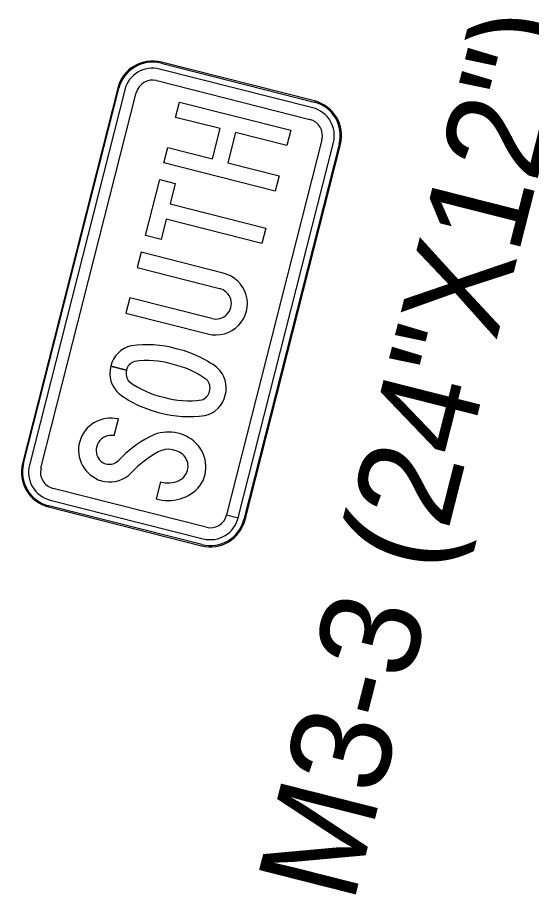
# Model space of a CAD drawing. Extents: x 670257 to 671518, y 737783 to 738188.
# Drawn here: x 670295.772 to 670297.06, y 738152.056 to 738154.257 of the extents above; entities that cross this region are included whole.
import ezdxf

# ---------------------------------------------------------------- set-up
doc = ezdxf.new("R2010")
doc.units = 0
doc.layers.add('R_SIGN_ANNOT', color=7, linetype='Continuous')
doc.layers.add('R_SIGN_HWY102', color=7, linetype='Continuous')

msp = doc.modelspace()

# ---------------------------------------------------------------- linework, layer by layer
at = {"layer": 'R_SIGN_HWY102'}
for p, q in [((670296.1321, 738154.1419), (670296.1321, 738154.1419)), ((670296.1321, 738154.1419), (670296.5157, 738154.0446)), ((670296.1329, 738154.1448), (670296.1328, 738154.1448)), ((670296.1329, 738154.1448), (670296.1328, 738154.1448)), ((670296.5165, 738154.0475), (670296.1329, 738154.1448)), ((670296.5165, 738154.0475), (670296.1329, 738154.1448)), ((670296.512, 738154.03), (670296.1284, 738154.1273)), ((670296.1284, 738154.1273), (670296.1284, 738154.1273)), ((670296.121, 738154.0983), (670296.1211, 738154.0983)), ((670296.1211, 738154.0983), (670296.5047, 738154.001)), ((670296.0236, 738154.0797), (670295.7847, 738153.1379)), ((670296.0236, 738154.0797), (670295.7847, 738153.1379)), ((670295.7876, 738153.1372), (670296.0265, 738154.0789)), ((670296.041, 738154.0753), (670295.8021, 738153.1335)), ((670296.0236, 738154.0797), (670296.0236, 738154.0797)), ((670296.0236, 738154.0797), (670296.0236, 738154.0797)), ((670296.0265, 738154.0789), (670296.0265, 738154.0789)), ((670296.041, 738154.0753), (670296.041, 738154.0753)), ((670295.8312, 738153.1261), (670296.0701, 738154.0679)), ((670296.0701, 738154.0679), (670296.07, 738154.0679)), ((670296.512, 738154.03), (670296.512, 738154.03)), ((670296.5157, 738154.0446), (670296.5157, 738154.0446)), ((670296.5165, 738154.0475), (670296.5165, 738154.0475)), ((670296.5165, 738154.0475), (670296.5165, 738154.0475)), ((670296.5047, 738154.001), (670296.5047, 738154.001)), ((670296.535, 738153.95), (670296.2962, 738153.0085)), ((670296.3253, 738153.0011), (670296.5641, 738153.9426)), ((670296.5786, 738153.9389), (670296.3397, 738152.9972)), ((670296.535, 738153.95), (670296.535, 738153.95)), ((670296.5641, 738153.9426), (670296.5641, 738153.9426)), ((670296.5786, 738153.9389), (670296.5786, 738153.9389)), ((670296.3427, 738152.9964), (670296.5815, 738153.9382)), ((670296.3427, 738152.9964), (670296.5815, 738153.9382)), ((670296.5815, 738153.9382), (670296.5815, 738153.9382)), ((670296.5815, 738153.9382), (670296.5815, 738153.9382)), ((670296.0437, 738153.5149), (670296.2494, 738153.4628)), ((670296.0437, 738153.5149), (670296.2494, 738153.4628)), ((670296.0437, 738153.5149), (670296.2494, 738153.4628)), ((670296.0455, 738153.3718), (670296.0063, 738153.3817)), ((670296.0063, 738153.3817), (670296.0455, 738153.3718)), ((670296.0455, 738153.3718), (670296.0063, 738153.3817)), ((670296.0063, 738153.3817), (670296.0455, 738153.3718)), ((670296.0146, 738153.2076), (670296.0252, 738153.2495)), ((670296.0146, 738153.2076), (670296.0252, 738153.2495)), ((670296.0146, 738153.2076), (670296.0252, 738153.2495)), ((670295.7847, 738153.1379), (670295.7847, 738153.1379)), ((670295.7847, 738153.1379), (670295.7847, 738153.1379)), ((670295.7876, 738153.1372), (670295.7876, 738153.1372)), ((670295.8021, 738153.1335), (670295.8021, 738153.1335)), ((670295.8312, 738153.1261), (670295.8312, 738153.1261)), ((670296.1307, 738153.0915), (670296.1199, 738153.049)), ((670296.1307, 738153.0915), (670296.1199, 738153.049)), ((670296.1307, 738153.0915), (670296.1199, 738153.049)), ((670296.2452, 738152.9778), (670295.8615, 738153.0751)), ((670295.8615, 738153.0751), (670295.8615, 738153.0751)), ((670295.8542, 738153.046), (670295.8542, 738153.046)), ((670295.8542, 738153.046), (670296.2378, 738152.9487)), ((670295.8497, 738153.0286), (670295.8498, 738153.0286)), ((670295.8497, 738153.0286), (670295.8498, 738153.0286)), ((670295.8498, 738153.0286), (670296.2334, 738152.9313)), ((670295.8498, 738153.0286), (670296.2334, 738152.9313)), ((670296.2341, 738152.9342), (670295.8505, 738153.0315)), ((670295.8505, 738153.0315), (670295.8505, 738153.0315)), ((670296.2962, 738153.0085), (670296.3253, 738153.0011)), ((670296.3252, 738153.0008), (670296.2962, 738153.0082)), ((670296.2962, 738153.0082), (670296.2962, 738153.0082)), ((670296.3252, 738153.0008), (670296.3252, 738153.0008)), ((670296.3397, 738152.9972), (670296.3427, 738152.9964)), ((670296.3427, 738152.9964), (670296.3397, 738152.9971)), ((670296.3397, 738152.9971), (670296.3397, 738152.9971)), ((670296.3426, 738152.9964), (670296.3427, 738152.9964)), ((670296.2452, 738152.9778), (670296.2452, 738152.9778)), ((670296.2378, 738152.9487), (670296.2378, 738152.9487)), ((670296.2334, 738152.9313), (670296.2334, 738152.9313)), ((670296.2334, 738152.9313), (670296.2334, 738152.9313)), ((670296.2341, 738152.9342), (670296.2341, 738152.9342))]:
    msp.add_line(p, q, dxfattribs=at)
for points in [[(670296.1393, 738153.892), (670296.1491, 738153.9305), (670296.2606, 738153.9022), (670296.2798, 738153.9778), (670296.1682, 738154.0061), (670296.178, 738154.0446), (670296.4569, 738153.9738), (670296.4472, 738153.9354), (670296.3189, 738153.9679), (670296.2997, 738153.8923), (670296.428, 738153.8597), (670296.4182, 738153.8213)], [(670296.1393, 738153.892), (670296.1491, 738153.9305), (670296.2606, 738153.9022), (670296.2798, 738153.9778), (670296.1682, 738154.0061), (670296.178, 738154.0446), (670296.4569, 738153.9738), (670296.4472, 738153.9354), (670296.3189, 738153.9679), (670296.2997, 738153.8923), (670296.428, 738153.8597), (670296.4182, 738153.8213)], [(670296.1393, 738153.892), (670296.1491, 738153.9305), (670296.2606, 738153.9022), (670296.2798, 738153.9778), (670296.1682, 738154.0061), (670296.178, 738154.0446), (670296.4569, 738153.9738), (670296.4472, 738153.9354), (670296.3189, 738153.9679), (670296.2997, 738153.8923), (670296.428, 738153.8597), (670296.4182, 738153.8213)], [(670296.145, 738153.7505), (670296.1321, 738153.6997), (670296.093, 738153.7096), (670296.1286, 738153.8498), (670296.1676, 738153.8399), (670296.1547, 738153.7891), (670296.3946, 738153.7282), (670296.3849, 738153.6897)], [(670296.145, 738153.7505), (670296.1321, 738153.6997), (670296.093, 738153.7096), (670296.1286, 738153.8498), (670296.1676, 738153.8399), (670296.1547, 738153.7891), (670296.3946, 738153.7282), (670296.3849, 738153.6897)], [(670296.145, 738153.7505), (670296.1321, 738153.6997), (670296.093, 738153.7096), (670296.1286, 738153.8498), (670296.1676, 738153.8399), (670296.1547, 738153.7891), (670296.3946, 738153.7282), (670296.3849, 738153.6897)]]:
    msp.add_lwpolyline(points, close=True, dxfattribs=at)
for points in [[(670296.2881, 738153.6153), (670296.0824, 738153.6675), (670296.0726, 738153.629), (670296.2783, 738153.5768)], [(670296.2881, 738153.6153), (670296.0824, 738153.6675), (670296.0726, 738153.629), (670296.2783, 738153.5768)], [(670296.2881, 738153.6153), (670296.0824, 738153.6675), (670296.0726, 738153.629), (670296.2783, 738153.5768)], [(670296.2591, 738153.5012), (670296.0534, 738153.5534), (670296.0437, 738153.5149)], [(670296.2591, 738153.5012), (670296.0534, 738153.5534), (670296.0437, 738153.5149)], [(670296.2591, 738153.5012), (670296.0534, 738153.5534), (670296.0437, 738153.5149)]]:
    msp.add_lwpolyline(points, dxfattribs=at)
for centre, major_axis, ratio, start_param, end_param in [((670296.1107, 738154.0576), (0.0221, 0.0872), 0.999584, 0, 1.570796), ((670296.1107, 738154.0576), (0.0221, 0.0872), 0.999584, 0, 1.570796), ((670296.1107, 738154.0576), (0.0214, 0.0843), 0.999584, 0, 1.570796), ((670296.1107, 738154.0576), (0.0177, 0.0698), 0.999584, 0, 1.570796), ((670296.1107, 738154.0576), (0.0103, 0.0407), 0.999584, 0, 1.570796), ((670296.4943, 738153.9603), (0.0177, 0.0698), 0.999584, 4.712389, 6.283185), ((670296.4943, 738153.9603), (0.0214, 0.0843), 0.999584, 4.712389, 6.283185), ((670296.4943, 738153.9603), (0.0221, 0.0872), 0.999584, 4.712389, 6.283185), ((670296.4943, 738153.9603), (0.0221, 0.0872), 0.999584, 4.712389, 6.283185), ((670296.4943, 738153.9603), (0.0103, 0.0407), 0.999584, 4.712389, 6.283185), ((670296.2687, 738153.539), (-0.0774, 0.0196), 0.985401, 1.570796, 4.712389), ((670296.2687, 738153.539), (-0.0774, 0.0196), 0.985401, 1.570796, 4.712389), ((670296.2687, 738153.539), (-0.0774, 0.0196), 0.985401, 1.570796, 4.712389), ((670296.2687, 738153.539), (-0.0384, 0.0097), 0.985401, 1.570796, 4.712389), ((670296.2687, 738153.539), (-0.0384, 0.0097), 0.985401, 1.570796, 4.712389), ((670296.2687, 738153.539), (-0.0384, 0.0097), 0.985401, 1.570796, 4.712389), ((670296.0725, 738153.3673), (-0.0657, 0.0167), 0.987317, 5.182411, 6.318105), ((670296.0725, 738153.3673), (-0.0657, 0.0167), 0.987317, 5.182411, 6.317893), ((670296.0725, 738153.3673), (-0.0657, 0.0167), 0.987317, 5.182411, 6.317893), ((670296.0985, 738153.1659), (-0.2645, 0.0671), 0.987317, 4.692766, 5.109028), ((670296.0985, 738153.1659), (-0.2645, 0.0671), 0.987317, 4.692766, 5.109028), ((670296.0985, 738153.1659), (-0.2645, 0.0671), 0.987317, 4.692766, 5.109028), ((670296.1089, 738153.1633), (-0.2645, 0.0671), 0.987317, 4.31575, 4.732012), ((670296.1089, 738153.1633), (-0.2645, 0.0671), 0.987317, 4.31575, 4.732012), ((670296.1089, 738153.1633), (-0.2645, 0.0671), 0.987317, 4.31575, 4.732012), ((670296.074, 738153.3661), (-0.0281, 0.0071), 0.987317, 5.258281, 6.33678), ((670296.074, 738153.3661), (-0.0281, 0.0071), 0.987317, 5.258281, 6.336283), ((670296.074, 738153.3661), (-0.0281, 0.0071), 0.987317, 5.258281, 6.336283), ((670296.0986, 738153.1841), (-0.2078, 0.0527), 0.987317, 4.667051, 5.113562), ((670296.0986, 738153.1841), (-0.2078, 0.0527), 0.987317, 4.667051, 5.113562), ((670296.0986, 738153.1841), (-0.2078, 0.0527), 0.987317, 4.667051, 5.113562), ((670296.0714, 738153.3628), (-0.0657, 0.0167), 0.987317, 6.248265, 7.383959), ((670296.0714, 738153.3628), (-0.0657, 0.0167), 0.987317, 6.248265, 7.383959), ((670296.0714, 738153.3628), (-0.0657, 0.0167), 0.987317, 6.248265, 7.383959), ((670296.0732, 738153.3631), (-0.0281, 0.0071), 0.987317, 6.22959, 7.30809), ((670296.0732, 738153.3631), (-0.0281, 0.0071), 0.987317, 6.22959, 7.30809), ((670296.0732, 738153.3631), (-0.0281, 0.0071), 0.987317, 6.22959, 7.30809), ((670296.1175, 738153.1793), (-0.2078, 0.0527), 0.987317, 4.311216, 4.757727), ((670296.1175, 738153.1793), (-0.2078, 0.0527), 0.987317, 4.311216, 4.757727), ((670296.1175, 738153.1793), (-0.2078, 0.0527), 0.987317, 4.311216, 4.757727), ((670296.2277, 738153.3279), (-0.0657, 0.0167), 0.987317, 3.106673, 4.242367), ((670296.2277, 738153.3279), (-0.0657, 0.0167), 0.987317, 3.106673, 4.242367), ((670296.2277, 738153.3279), (-0.0657, 0.0167), 0.987317, 3.106673, 4.242367), ((670296.2259, 738153.3276), (-0.0281, 0.0071), 0.987317, 3.087997, 4.166497), ((670296.2259, 738153.3276), (-0.0281, 0.0071), 0.987317, 3.087997, 4.166497), ((670296.2259, 738153.3276), (-0.0281, 0.0071), 0.987317, 3.087997, 4.166497), ((670296.1816, 738153.5114), (-0.2078, 0.0527), 0.987317, 1.169623, 1.616135), ((670296.1816, 738153.5114), (-0.2078, 0.0527), 0.987317, 1.169623, 1.616135), ((670296.1816, 738153.5114), (-0.2078, 0.0527), 0.987317, 1.169623, 1.616135), ((670296.1902, 738153.5274), (-0.2645, 0.0671), 0.987317, 1.174158, 1.59042), ((670296.1902, 738153.5274), (-0.2645, 0.0671), 0.987317, 1.174158, 1.59042), ((670296.1902, 738153.5274), (-0.2645, 0.0671), 0.987317, 1.174158, 1.59042), ((670296.2005, 738153.5066), (-0.2078, 0.0527), 0.987317, 1.525458, 1.97197), ((670296.2005, 738153.5066), (-0.2078, 0.0527), 0.987317, 1.525458, 1.97197), ((670296.2005, 738153.5066), (-0.2078, 0.0527), 0.987317, 1.525458, 1.97197), ((670296.2251, 738153.3246), (-0.0281, 0.0071), 0.987317, 2.116688, 3.195188), ((670296.2251, 738153.3246), (-0.0281, 0.0071), 0.987317, 2.116688, 3.195188), ((670296.2251, 738153.3246), (-0.0281, 0.0071), 0.987317, 2.116688, 3.195188), ((670296.2266, 738153.3234), (-0.0657, 0.0167), 0.987317, 2.040819, 3.176513), ((670296.2266, 738153.3234), (-0.0657, 0.0167), 0.987317, 2.040819, 3.176513), ((670296.2266, 738153.3234), (-0.0657, 0.0167), 0.987317, 2.040819, 3.176513), ((670296.0073, 738153.1708), (-0.0796, 0.0202), 0.981581, 4.736267, 7.790596), ((670296.0073, 738153.1708), (-0.0796, 0.0202), 0.981581, 4.736267, 7.790596), ((670296.0073, 738153.1708), (-0.0796, 0.0202), 0.981581, 4.736267, 7.790596), ((670296.2006, 738153.5248), (-0.2645, 0.0671), 0.987317, 1.551173, 1.967435), ((670296.2006, 738153.5248), (-0.2645, 0.0671), 0.987317, 1.551173, 1.967435), ((670296.2006, 738153.5248), (-0.2645, 0.0671), 0.987317, 1.551173, 1.967435), ((670296.1513, 738153.1201), (-0.0951, 0.0241), 0.981581, 4.260987, 5.485755), ((670296.1513, 738153.1201), (-0.0951, 0.0241), 0.981581, 4.260987, 5.485755), ((670296.1513, 738153.1201), (-0.0951, 0.0241), 0.981581, 4.260987, 5.485755), ((670296.0081, 738153.1702), (-0.0374, 0.0095), 0.981581, 4.786904, 7.140738), ((670296.0081, 738153.1702), (-0.0374, 0.0095), 0.981581, 4.786904, 7.140738), ((670296.0081, 738153.1702), (-0.0374, 0.0095), 0.981581, 4.786904, 7.140738), ((670296.249, 738152.9415), (-0.2944, 0.0747), 0.981581, 5.462886, 5.782242), ((670296.249, 738152.9415), (-0.2944, 0.0747), 0.981581, 5.462886, 5.782242), ((670296.249, 738152.9415), (-0.2944, 0.0747), 0.981581, 5.462886, 5.782242), ((670296.1584, 738153.1296), (-0.0835, 0.0212), 0.981581, 2.786047, 4.251692), ((670296.1584, 738153.1296), (-0.0835, 0.0212), 0.981581, 2.786047, 4.251692), ((670296.1584, 738153.1296), (-0.0835, 0.0212), 0.981581, 2.786047, 4.251692), ((670296.151, 738153.1194), (-0.0531, 0.0135), 0.981581, 4.254409, 5.632398), ((670296.151, 738153.1194), (-0.0531, 0.0135), 0.981581, 4.254409, 5.632398), ((670296.151, 738153.1194), (-0.0531, 0.0135), 0.981581, 4.254409, 5.632398), ((670296.0022, 738153.1668), (-0.0309, 0.0078), 0.981581, 0.87378, 2.656959), ((670296.0022, 738153.1668), (-0.0309, 0.0078), 0.981581, 0.87378, 2.656959), ((670296.0022, 738153.1668), (-0.0309, 0.0078), 0.981581, 0.87378, 2.656959), ((670296.2866, 738152.893), (-0.3108, 0.0788), 0.981581, 5.515137, 5.786988), ((670296.2866, 738152.893), (-0.3108, 0.0788), 0.981581, 5.515137, 5.786988), ((670296.2866, 738152.893), (-0.3108, 0.0788), 0.981581, 5.515137, 5.786988), ((670296.1597, 738153.1309), (-0.0389, 0.0099), 0.981581, 2.261787, 4.23006), ((670296.1597, 738153.1309), (-0.0389, 0.0099), 0.981581, 2.261787, 4.23006), ((670296.1597, 738153.1309), (-0.0389, 0.0099), 0.981581, 2.261787, 4.23006), ((670295.8719, 738153.1158), (0.0221, 0.0872), 0.999584, 1.570796, 3.141593), ((670295.8719, 738153.1158), (0.0221, 0.0872), 0.999584, 1.570796, 3.141593), ((670295.8719, 738153.1158), (0.0214, 0.0843), 0.999584, 1.570796, 3.141593), ((670295.8719, 738153.1158), (0.0177, 0.0698), 0.999584, 1.570796, 3.141593), ((670295.8719, 738153.1158), (0.0103, 0.0407), 0.999584, 1.570796, 3.141593), ((670296.0028, 738153.1636), (-0.0715, 0.0181), 0.981581, 1.534831, 2.511766), ((670296.0028, 738153.1636), (-0.0715, 0.0181), 0.981581, 1.534831, 2.511766), ((670296.0028, 738153.1636), (-0.0715, 0.0181), 0.981581, 1.534831, 2.511766), ((670296.1493, 738153.1462), (-0.1003, 0.0254), 0.981581, 1.526364, 2.701682), ((670296.1493, 738153.1462), (-0.1003, 0.0254), 0.981581, 1.526364, 2.701682), ((670296.1493, 738153.1462), (-0.1003, 0.0254), 0.981581, 1.526364, 2.701682), ((670296.1487, 738153.1507), (-0.0611, 0.0155), 0.981581, 1.524757, 2.28214), ((670296.1487, 738153.1507), (-0.0611, 0.0155), 0.981581, 1.524757, 2.28214), ((670296.1487, 738153.1507), (-0.0611, 0.0155), 0.981581, 1.524757, 2.28214), ((670296.2555, 738153.0185), (0.0221, 0.0872), 0.999584, 3.141593, 4.712389), ((670296.2555, 738153.0185), (0.0221, 0.0872), 0.999584, 3.141593, 4.712389), ((670296.2555, 738153.0185), (0.0214, 0.0843), 0.999584, 3.141593, 4.712389), ((670296.2555, 738153.0185), (0.0177, 0.0698), 0.999584, 3.141593, 4.712389), ((670296.2555, 738153.0185), (0.0103, 0.0407), 0.999584, 3.141593, 4.712389)]:
    msp.add_ellipse(centre, major_axis=major_axis, ratio=ratio, start_param=start_param, end_param=end_param, dxfattribs=at)

# ---------------------------------------------------------------- texts
at = {"layer": 'R_SIGN_ANNOT'}
msp.add_text('M3-3 (24"X12")', height=0.25, rotation=75.7686, dxfattribs=at).set_placement((670296.6133, 738152.0297))

doc.saveas('drawing.dxf')
